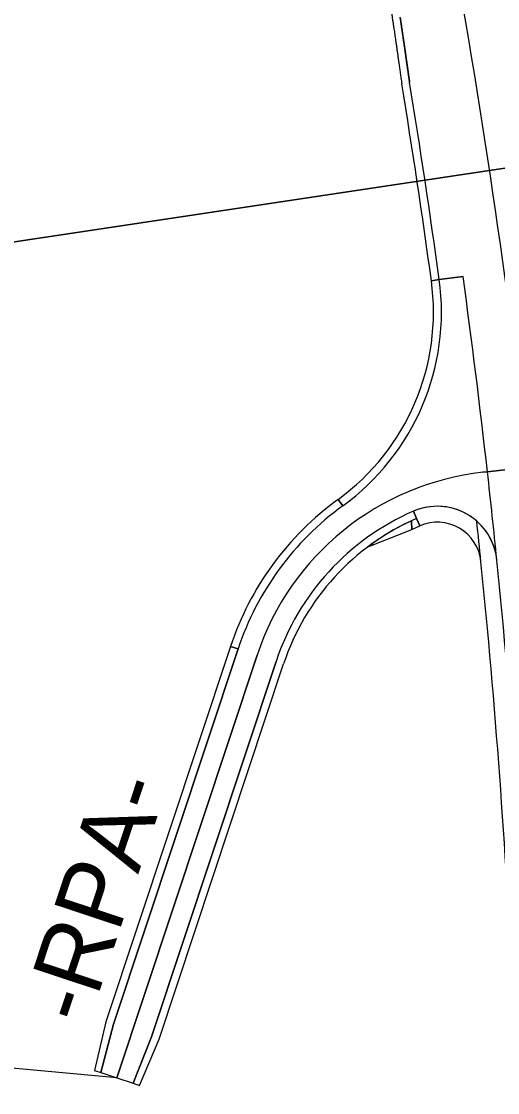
# Model space of a CAD drawing. Extents: x 1805231 to 1809482, y 908883 to 918297.
# Drawn here: x 1807610 to 1807848, y 914790 to 915327 of the extents above; entities that cross this region are included whole.
import ezdxf

# ---------------------------------------------------------------- set-up
doc = ezdxf.new("R2010")
doc.units = 0
for name, color, linetype in [('Prop DSN Text', 7, 'Continuous'), ('Prop Horizontal Alignment Station Label', 7, 'Continuous'), ('Prop Shade Medium', 7, 'Continuous')]:
    doc.layers.add(name, color=color, linetype=linetype)

msp = doc.modelspace()

# ---------------------------------------------------------------- linework, layer by layer
at = {"layer": 'Prop DSN Text'}
for p, q in [((1807800.22, 915296.15), (1807800.2, 915296.23)), ((1807800.2, 915296.23), (1807800.22, 915296.15)), ((1807815.03, 915197.4), (1807815.06, 915197.41)), ((1807815.06, 915197.41), (1807815.03, 915197.4)), ((1807818.99, 915197.95), (1807815.06, 915197.41)), ((1807818.99, 915197.95), (1807815.06, 915197.41)), ((1807815.06, 915197.41), (1807818.99, 915197.95)), ((1807830.88, 915199.58), (1807818.99, 915197.95)), ((1807818.99, 915197.95), (1807830.88, 915199.58)), ((1807830.88, 915199.58), (1807818.99, 915197.95)), ((1807840.83, 915101.38), (1807843.11, 915101.64)), ((1807843.11, 915101.64), (1807840.83, 915101.38)), ((1807843.11, 915101.64), (1807863.73, 915103.95)), ((1807863.73, 915103.95), (1807843.11, 915101.64)), ((1807768.3, 915087.76), (1807770.65, 915084.52)), ((1807770.65, 915084.52), (1807768.3, 915087.76)), ((1807768.3, 915087.76), (1807770.65, 915084.52)), ((1807807.61, 915078.17), (1807806.02, 915081.84)), ((1807809.21, 915074.51), (1807806.02, 915081.84)), ((1807806.02, 915081.84), (1807807.61, 915078.17)), ((1807805.23, 915072.77), (1807809.21, 915074.51)), ((1807807.61, 915078.17), (1807809.21, 915074.51)), ((1807809.21, 915074.51), (1807807.61, 915078.17)), ((1807785.33, 915064.83), (1807804.38, 915072.41)), ((1807804.38, 915072.41), (1807805.23, 915072.77)), ((1807783.3, 915064.03), (1807785.33, 915064.83)), ((1807785.31, 915065.51), (1807785.33, 915064.83)), ((1807785.33, 915064.83), (1807785.31, 915065.51)), ((1807714.46, 915014.12), (1807652.08, 914825.98)), ((1807655.88, 914824.72), (1807718.26, 915012.86)), ((1807718.26, 915012.86), (1807655.88, 914824.72)), ((1807657.5, 914797.84), (1807727.75, 915009.71)), ((1807727.75, 915009.71), (1807657.5, 914797.84)), ((1807718.26, 915012.86), (1807714.46, 915014.12)), ((1807718.26, 915012.86), (1807714.46, 915014.12)), ((1807714.46, 915014.12), (1807718.26, 915012.86)), ((1807737.24, 915006.56), (1807674.86, 914818.42)), ((1807674.86, 914818.42), (1807737.24, 915006.56)), ((1807678.66, 914817.17), (1807741.04, 915005.3)), ((1807652.08, 914825.98), (1807646.36, 914801.54)), ((1807649.52, 914800.49), (1807655.88, 914824.72)), ((1807655.88, 914824.72), (1807649.52, 914800.49)), ((1807674.86, 914818.42), (1807665.62, 914795.15)), ((1807665.62, 914795.15), (1807674.86, 914818.42)), ((1807668.94, 914794.05), (1807678.66, 914817.17)), ((1807646.36, 914801.54), (1807649.52, 914800.49)), ((1807649.52, 914800.49), (1807657.5, 914797.84)), ((1807657.5, 914797.84), (1807665.62, 914795.15)), ((1807665.62, 914795.15), (1807668.94, 914794.05))]:
    msp.add_line(p, q, dxfattribs=at)
for points in [[(1807805.23, 915072.77), (1807805.13, 915076.76), (1807805.13, 915077.06)], [(1807805.13, 915077.06), (1807805.13, 915076.76), (1807805.23, 915072.77)]]:
    msp.add_lwpolyline(points, dxfattribs=at)
for centre, radius, start, end in [((1803888.72, 914657.58), 4000, 6.4071, 10.37717), ((1803888.72, 914657.58), 4000, 6.4071, 10.37717), ((1803888.72, 914657.58), 3963.28, 7.82835, 9.27189), ((1803888.72, 914657.58), 3967.25, 7.82835, 9.27189), ((1803888.72, 914657.58), 3967.25, 9.271889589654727, 9.2718898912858), ((1803888.72, 914657.58), 3967.25, 7.82835, 9.27189), ((1807700.11, 915181.6), 116, 306.0041, 7.8283), ((1807700.11, 915181.6), 120, 306.0041, 7.8283), ((1807700.11, 915181.6), 120, 306.0041, 7.8283), ((1803888.72, 914657.58), 3979.25, 6.4071, 7.82835), ((1803888.72, 914657.58), 3979.25, 6.4071, 7.82835), ((1807855.89, 914967.22), 135, 96.4071, 161.6564), ((1807855.89, 914967.22), 135, 96.4071, 161.6564), ((1803888.72, 914657.58), 3979.25, 5.76578, 6.4071), ((1803888.72, 914657.58), 3979.25, 5.76578, 6.4071), ((1807855.89, 914967.22), 149, 126.0041, 161.6564), ((1807855.89, 914967.22), 145, 126.0041, 161.6564), ((1807855.89, 914967.22), 145, 126.0041, 161.6564), ((1807817.99, 915054.33), 30, 5.7658, 113.5151), ((1807817.99, 915054.33), 30, 48.747, 113.5151), ((1807855.89, 914967.22), 125, 113.5151, 161.6564), ((1807855.89, 914967.22), 125, 113.5151, 161.6564), ((1807855.89, 914967.22), 121, 113.5151, 161.6564), ((1807855.89, 914967.22), 121, 114.8051, 125.683), ((1807855.89, 914967.22), 121, 113.5151, 114.8051), ((1807817.99, 915054.33), 22, 5.7658, 113.5151), ((1807817.99, 915054.33), 22, 5.7658, 113.5151), ((1803888.72, 914657.58), 3971.25, 5.76578, 6.06087), ((1807817.99, 915054.33), 30, 5.7658, 48.747), ((1803888.72, 914657.58), 3971.25, 5.76578, 6.06087), ((1807855.89, 914967.22), 121, 125.683, 126.8654), ((1803888.72, 914657.58), 3979.25, 2.65322, 5.76578), ((1803888.72, 914657.58), 3979.25, 2.65322, 5.76578), ((1803888.72, 914657.58), 3971.25, 2.65322, 5.76578)]:
    msp.add_arc(centre, radius, start, end, dxfattribs=at)
for points, degree in [([(1807792.99, 915345.26), (1807795.5, 915328.93), (1807797.9, 915312.59), (1807800.2, 915296.23)], 2), ([(1807799.42, 915329.29), (1807799.42, 915329.29), (1807799.42, 915329.29), (1807799.42, 915329.29), (1807799.45, 915329.07), (1807799.49, 915328.85), (1807799.52, 915328.63), (1807799.55, 915328.41), (1807799.58, 915328.19), (1807799.62, 915327.97), (1807799.65, 915327.75), (1807799.68, 915327.53), (1807799.72, 915327.3), (1807799.75, 915327.08), (1807799.78, 915326.86), (1807799.81, 915326.64), (1807799.85, 915326.42), (1807799.88, 915326.2), (1807799.91, 915325.98), (1807799.95, 915325.76), (1807799.98, 915325.54), (1807800.01, 915325.31), (1807800.04, 915325.09), (1807800.08, 915324.87), (1807800.11, 915324.65), (1807800.14, 915324.43), (1807800.18, 915324.21), (1807800.21, 915323.99), (1807800.24, 915323.77), (1807800.27, 915323.55), (1807800.31, 915323.33), (1807800.34, 915323.1), (1807800.37, 915322.88), (1807800.4, 915322.66), (1807800.44, 915322.44), (1807800.47, 915322.22), (1807800.5, 915322), (1807800.53, 915321.78), (1807800.57, 915321.56), (1807800.6, 915321.34), (1807800.63, 915321.11), (1807800.66, 915320.89), (1807800.7, 915320.67), (1807800.73, 915320.45), (1807800.76, 915320.23), (1807800.79, 915320.01), (1807800.83, 915319.79), (1807800.86, 915319.57), (1807800.89, 915319.35), (1807800.92, 915319.12), (1807800.96, 915318.9), (1807800.99, 915318.68), (1807801.02, 915318.46), (1807801.05, 915318.24), (1807801.09, 915318.02), (1807801.12, 915317.8), (1807801.15, 915317.58), (1807801.18, 915317.36), (1807801.22, 915317.13), (1807801.25, 915316.91), (1807801.28, 915316.69), (1807801.31, 915316.47), (1807801.34, 915316.25), (1807801.38, 915316.03), (1807801.41, 915315.81), (1807801.44, 915315.59), (1807801.47, 915315.37), (1807801.51, 915315.14), (1807801.54, 915314.92), (1807801.57, 915314.7), (1807801.57, 915314.69), (1807801.57, 915314.68), (1807801.57, 915314.67)], 3), ([(1807801.57, 915314.67), (1807801.61, 915314.46), (1807801.64, 915314.25), (1807801.67, 915314.04), (1807801.68, 915313.91), (1807801.7, 915313.78), (1807801.72, 915313.65)], 3), ([(1807801.72, 915313.65), (1807801.74, 915313.56), (1807801.75, 915313.47), (1807801.76, 915313.38), (1807801.77, 915313.3), (1807801.78, 915313.23), (1807801.79, 915313.16)], 3), ([(1807804.13, 915296.79), (1807804.1, 915297.01), (1807804.07, 915297.23), (1807804.04, 915297.45), (1807804.01, 915297.67), (1807803.98, 915297.89), (1807803.95, 915298.11), (1807803.91, 915298.33), (1807803.88, 915298.56), (1807803.85, 915298.78), (1807803.82, 915299), (1807803.79, 915299.22), (1807803.76, 915299.44), (1807803.73, 915299.66), (1807803.7, 915299.88), (1807803.66, 915300.1), (1807803.63, 915300.33), (1807803.6, 915300.55), (1807803.57, 915300.77), (1807803.54, 915300.99), (1807803.51, 915301.21), (1807803.48, 915301.43), (1807803.44, 915301.65), (1807803.41, 915301.87), (1807803.38, 915302.1), (1807803.35, 915302.32), (1807803.32, 915302.54), (1807803.29, 915302.76), (1807803.26, 915302.98), (1807803.22, 915303.2), (1807803.19, 915303.42), (1807803.16, 915303.64), (1807803.13, 915303.86), (1807803.1, 915304.09), (1807803.07, 915304.31), (1807803.04, 915304.53), (1807803, 915304.75), (1807802.97, 915304.97), (1807802.94, 915305.19), (1807802.91, 915305.41), (1807802.88, 915305.63), (1807802.85, 915305.86), (1807802.81, 915306.08), (1807802.78, 915306.3), (1807802.75, 915306.52), (1807802.72, 915306.74), (1807802.69, 915306.96), (1807802.66, 915307.18), (1807802.62, 915307.4), (1807802.59, 915307.63), (1807802.56, 915307.85), (1807802.53, 915308.07), (1807802.5, 915308.29), (1807802.46, 915308.51), (1807802.43, 915308.73), (1807802.4, 915308.95), (1807802.37, 915309.17), (1807802.34, 915309.39), (1807802.31, 915309.62), (1807802.27, 915309.84), (1807802.24, 915310.06), (1807802.21, 915310.28), (1807802.18, 915310.5), (1807802.15, 915310.72), (1807802.11, 915310.94), (1807802.08, 915311.16), (1807802.05, 915311.39), (1807802.02, 915311.61), (1807801.99, 915311.83), (1807801.95, 915312.05), (1807801.92, 915312.27), (1807801.89, 915312.49), (1807801.86, 915312.71), (1807801.84, 915312.86), (1807801.82, 915313.01), (1807801.79, 915313.16)], 3), ([(1807801.79, 915313.16), (1807801.82, 915313.01), (1807801.84, 915312.86), (1807801.86, 915312.71), (1807801.89, 915312.49), (1807801.92, 915312.27), (1807801.95, 915312.05), (1807801.99, 915311.83), (1807802.02, 915311.61), (1807802.05, 915311.39), (1807802.08, 915311.16), (1807802.11, 915310.94), (1807802.15, 915310.72), (1807802.18, 915310.5), (1807802.21, 915310.28), (1807802.24, 915310.06), (1807802.27, 915309.84), (1807802.31, 915309.62), (1807802.34, 915309.39), (1807802.37, 915309.17), (1807802.4, 915308.95), (1807802.43, 915308.73), (1807802.46, 915308.51), (1807802.5, 915308.29), (1807802.53, 915308.07), (1807802.56, 915307.85), (1807802.59, 915307.63), (1807802.62, 915307.4), (1807802.66, 915307.18), (1807802.69, 915306.96), (1807802.72, 915306.74), (1807802.75, 915306.52), (1807802.78, 915306.3), (1807802.81, 915306.08), (1807802.85, 915305.86), (1807802.88, 915305.63), (1807802.91, 915305.41), (1807802.94, 915305.19), (1807802.97, 915304.97), (1807803, 915304.75), (1807803.04, 915304.53), (1807803.07, 915304.31), (1807803.1, 915304.09), (1807803.13, 915303.86), (1807803.16, 915303.64), (1807803.19, 915303.42), (1807803.22, 915303.2), (1807803.26, 915302.98), (1807803.29, 915302.76), (1807803.29, 915302.72), (1807803.3, 915302.69), (1807803.3, 915302.65)], 3), ([(1807803.3, 915302.65), (1807803.33, 915302.47), (1807803.36, 915302.28), (1807803.38, 915302.1), (1807803.41, 915301.87), (1807803.44, 915301.65), (1807803.48, 915301.43), (1807803.51, 915301.21), (1807803.54, 915300.99), (1807803.57, 915300.77), (1807803.6, 915300.55), (1807803.63, 915300.33), (1807803.66, 915300.1), (1807803.7, 915299.88), (1807803.73, 915299.66), (1807803.76, 915299.44), (1807803.79, 915299.22), (1807803.82, 915299), (1807803.85, 915298.78), (1807803.88, 915298.56), (1807803.91, 915298.33), (1807803.95, 915298.11), (1807803.98, 915297.89), (1807804.01, 915297.67), (1807804.04, 915297.45), (1807804.07, 915297.23), (1807804.1, 915297.01), (1807804.13, 915296.79)], 3)]:
    msp.add_open_spline(points, degree=degree, dxfattribs=at)
msp.add_spline([(1807801.79, 915313.16), (1807801.76, 915313.38), (1807801.67, 915314.04), (1807801.57, 915314.7), (1807801.47, 915315.37), (1807801.38, 915316.03), (1807801.28, 915316.69), (1807801.18, 915317.36), (1807801.09, 915318.02), (1807800.99, 915318.68), (1807800.89, 915319.35), (1807800.79, 915320.01), (1807800.7, 915320.67), (1807800.6, 915321.34), (1807800.5, 915322), (1807800.4, 915322.66), (1807800.31, 915323.33), (1807800.21, 915323.99), (1807800.11, 915324.65), (1807800.01, 915325.31), (1807799.91, 915325.98), (1807799.81, 915326.64), (1807799.72, 915327.3), (1807799.62, 915327.97), (1807799.52, 915328.63), (1807799.42, 915329.29), (1807799.39, 915329.52)], degree=3, dxfattribs=at)
at = {"layer": 'Prop Horizontal Alignment Station Label'}
msp.add_line((1807657.5, 914797.84), (1807037.39, 914855.72), dxfattribs=at)
at = {"layer": 'Prop Shade Medium'}
for points in [[(1808257.25, 915314.81), (1808192.53, 916618.4), (1807143.82, 916566.34), (1807143.82, 916566.34), (1807144.37, 916566.36), (1807218.2, 915068.18), (1807212.6, 915180.97), (1807443.97, 915192.45)], [(1807282.66, 913769.83), (1808331.37, 913821.9), (1808257.25, 915314.81), (1807443.97, 915192.45), (1807212.6, 915180.97), (1807218.2, 915068.18)]]:
    msp.add_lwpolyline(points, close=True, dxfattribs=at)

# ---------------------------------------------------------------- texts
at = {"layer": 'Prop Horizontal Alignment Station Label'}
msp.add_text('-RPA-', height=35, rotation=71.6564, dxfattribs=at).set_placement((1807642.82, 914823.11))

doc.saveas('drawing.dxf')
